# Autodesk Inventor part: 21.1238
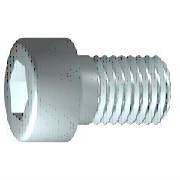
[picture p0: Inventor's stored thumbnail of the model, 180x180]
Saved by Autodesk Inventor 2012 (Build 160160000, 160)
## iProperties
Created: 2006-02
Part Number: 21.1238
Material: Steel, Mild
Description: M6 x 16 Socket Head Cap Screw
Document SubType Name: Modeling
Standard: DIN 7984
Designer: Andy Moles
Standards Organization: DIN
Language: en-US
Size Designation: M6 x 16
Categories: <MemberInstance><Categories><Category DisplayName="Fasteners" InternalName="e4da775c-781d-43d5-af7c-5136215cf5a6" Mnemonic="FSTN"><Category DisplayName="Bolts"
Density: 7.86 g/cm^3
Mass: 5.59687 g
Surface Area: 6.14162 cm^2
Volume: 0.71207 cm^3
Vendor: S
Author: Andy Moles
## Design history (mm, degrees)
body "Solid1"
workplane "Work Plane1"
revolve "Body" stored, may be unused: angle "d10" = 90 deg
sketch "Sketch2"
  geometry: L1 (0, -6)-(0, 8) reference; L2 (-6, 0)-(8, 0) reference; L3 (2.309, 0)-(1.155, -2); L4 (1.155, -2)-(-1.155, -2); L5 (-1.155, -2)-(-2.309, 0); L6 (-2.309, 0)-(-1.155, 2); L7 (-1.155, 2)-(1.155, 2); L8 (1.155, 2)-(2.309, 0); 2 further points
  constraints: 12 end point, 1 coincident, 1 horizontal alignment, 1 point on line, 12 other
extrude "Slot" join sketch "Sketch2" stored distance "d11" = 10; taper "d12" = 0 deg
fillet "Fillet1" dims "d17" = 0.6 (= RR)
feature "Thread" dims "d13" = 16, "d14" = 0
chamfer "Chamfer1" distance "d15" = 0.61345 (= -0.5 x SPD + 0.5 x GD); stored, may be unused: second distance "d16" = 0.61345 (= GUL), angle "d27" = 45 deg
sketch "Sketch1"
  geometry: L1 (0.333, 0)-(16, 0); L2 (16, 0)-(16, 3); L3 (16, 3)-(3, 3); L4 (3, 3)-(2.386, 3); L5 (2.386, 3)-(0, 3); L6 (0, 3)-(0, 5); L7 (0, 5)-(-4, 5); L8 (-4, 5)-(-4, 2.309); L9 (-4, 2.309)-(-1, 2.309); L10 (-1, 2.309)-(0.333, 0); L11 (-6, 0)-(22, 0) reference; L12 (0, -0.5)-(0, 6.5) reference; L13 (3, 3)-(0, 3)
  constraints: 22 end point, 6 parallel, 2 collinear, 2 perpendicular, 1 horizontal, 1 midpoint
  dimensions: "d1" = 13 distance from line of L3.end L2 (= GEL); "d2" = 0.61355 distance of L4.end L3.end (computed from GAL); "d3" = 4 distance between parallel lines of L8 L6 (= KOH); "d4" = 3 distance of L8.end L9.end (= INTI); "d5" = 60 deg angle of L10 L1; "d6" = 6 diameter of L3 L1 (= GD); "d7" = 6 diameter of L5 L1 (= BDM); "d8" = 4.6188 diameter of L9 L1 (= 1.1547 x SW); "d9" = 10 diameter of L7 L1 (= KOD); "d26" = 16 distance between parallel lines of L12 L2 (= NLG)
other parameters: "GD" = 6 (= NND) [user parameter; used in 2 equation terms], "NLG" = 16 [user parameter; used in 1 equation term], "GEL" = 13 [user parameter; used in 1 equation term], "KOD" = 10 [user parameter; used in 1 equation term], "KOH" = 4 [user parameter; used in 1 equation term], "INTI" = 3 [user parameter; used in 1 equation term], "GAL" = 0.61345 (= 0.61345 x PTC) [user parameter; used in 1 equation term], "GUL" = 0.61345 (= 0.61345 x PTC) [user parameter; used in 1 equation term], "BDM" = 6 (= NND) [user parameter; used in 1 equation term], "SW" = 4 [user parameter; used in 2 equation terms], "RR" = 0.6 [user parameter; used in 1 equation term], "SPD" = 4.7731 (= NND - 1.2269 x PTC) [user parameter; used in 1 equation term], "d19" = 0, "d28" = 0, "d29" = 0, "TOA" = 30 deg [user parameter], "GD1" = 4.7731 (= THREADDIA - 1.2269 x PTC) [user parameter], "THREADDIA" = 6 [user parameter; used in 1 equation term], "FAWI" = 45 deg [user parameter], "ANG" = 120 deg [user parameter], "PTC" = 1 [user parameter; used in 5 equation terms], "NND" = 6 [user parameter; used in 3 equation terms], "E0" = 4.62 (= 1.155 x SW) [user parameter]
